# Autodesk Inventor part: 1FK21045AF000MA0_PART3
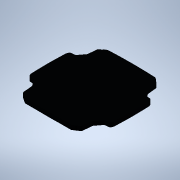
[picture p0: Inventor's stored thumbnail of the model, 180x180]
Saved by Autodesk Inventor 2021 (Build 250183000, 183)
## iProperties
Created: 2025-04
Part Number: 1FK21045AF000MA0_PART3
Material: Generic
Catalog Web Link: www.3dfindit.com
Description: -Servo synchronous motor
Document SubType Name: Modeling
Designer: psAdmin
Mass: 21.7019 g
Surface Area: 120.085 cm^2
Volume: 21.7019 cm^3
Density: 1 g/cm^3
Appearance: PSOLRGB-38-46-56
Category: PARTsolutions
Title: 1FK21045AF000MA0_PART3
Author: Cadenas PARTsolutions
Comments: Servo synchronous motor
Sending System: PARTsolutions
Preprocessor: ST-DEVELOPER v19.3
PSOL_IDENT_0: {$CADENAS_DATA/23d-libs/siemens_ag/_cat_/8b/0a/1fk21045af000ma0.prj},213 {VTYP=3D},{NB=1FK21045AF000
PSOL_IDENT_1: MA0_PART3},{LINA=1FK21045AF000MA0_PART3},{NN=1FK21045AF000MA0_PART3},{NOPRJ=TRUE},{DATE=19.08.2025 1
PSOL_IDENT_2: 4:00:48},{GEOMDATE=30.07.2025 02:00:28},{VERSION=},{LINEID=10},{WBVAR=},{WBNUMERIC=}  {NB=1FK21045AF
PSOL_IDENT_3: 000MA0_PART3},{LINA=1FK21045AF000MA0_PART3},{KT=DUMMY},{PREVIEW=../../../_pool_/a9/69/p_d211_xx_0081
PSOL_IDENT_4: 8j.png},{DESCSHORT=SIMOTICS S-1FK2 HD, SINAMICS S210 3AC 400V-480V, 2.4 Nm, 3000 rpm},{DESCLONG=SIMO
PSOL_IDENT_5: TICS S-1FK2 HD servo motor M0=2.4 Nm; PN = 0.75 kW at nN=3000 rpm (380-480 V); PN = 0.375 kW at nN=1
PSOL_IDENT_6: 500 rpm (200-240 V); degree of protection IP64; cylindrical shaft D19x40mm; absolute encoder 22-bit
PSOL_IDENT_7: + 12-bit multiturn (encoder AM22DQC); with OCC interface; plug size M17, rotatable; SIMOTICS S-1FK2
PSOL_IDENT_8: servomotorfor a wide range of uses in industrial environments. SIMOTICS S‑1FK2 servomotors are compa
PSOL_IDENT_9: ct synchronous motors with a high dynamic performance that set themselves apart as a result of their
PSOL_IDENT_10: high power density, degree of protection and overload capability. The motors are available in two v
PSOL_IDENT_11: ariants: as High Dynamic variant (highest dynamic performance as a result of the low intrinsic momen
PSOL_IDENT_12: t of inertia for applications demanding a high dynamic performance with low moved masses) - and as C
PSOL_IDENT_13: ompact variant (precise and stable closed-loop control for medium up to large moved masses as a resu
PSOL_IDENT_14: lt of a medium intrinsic moment of inertia). SIMOTICSS‑1FK2 servomotors fully exploit their strength
PSOL_IDENT_15: s in a system with the SINAMICSS210 frequency converter and simple connection using the one cable co
PSOL_IDENT_16: nnection (OCC). Advantages include the short control and positioning times, fast and precise correct
PSOL_IDENT_17: ion of disturbing quantities as well as stable control with a high dynamic performance. The servo mo
PSOL_IDENT_18: tors can be configured to address a wide range of requirements. For example with and without holding
PSOL_IDENT_19: brake, IP64 or IP65 degree of protection, singleturn or multiturn absolute encoders - to name just
PSOL_IDENT_20: a few. Further, the servomotors are available in different shaft heights extending from 20 to 100. A
PSOL_IDENT_21: shaft sealing ring is available to achieve an IP65 degree of protection and for subsequent mounting
PSOL_IDENT_22: at the motor or as spare part. SIMOTICS - the optimum motor for each and every motion control appli
PSOL_IDENT_23: cation.},{INTNO=195125050112},{SUPPLIERALTNO=1FK2104-5AF00-0MA0},{MANUID=1FK21045AF000MA0},{MANUNAME=
PSOL_IDENT_24: Siemens},{MANUTYPEDESC=Synchronous motor 1FK2-HD 2.4 NM},{AAU732=SIMOTICS},{AAO057=S-1FK2},{AAU734=S
PSOL_IDENT_25: IMOTICS S-1FK2 HD servo motor M0=2.4 Nm; PN = 0.75 kW at nN=3000 rpm (380-480 V); PN = 0.375 kW at n
PSOL_IDENT_26: N=1500 rpm (200-240 V); degree of protection IP64; cylindrical shaft D19x40mm; absolute encoder 22-b
PSOL_IDENT_27: it + 12-bit multiturn (encoder AM22DQC); with OCC interface; plug size M17, rotatable;},{AAW338=Sync
PSOL_IDENT_28: hronous motor 1FK2-HD 2.4 NM},{AAO742=SIMOTICS},{AAO663=4042948692912},{NOCUPEROU=1},{PRICEQUANTITY=
PSOL_IDENT_29: 1},{QUANTITYMIN=1},{QUANTITYINT=1},{CTN=85015100},{COO=DE},{AAO676=1FK2104-5AF00-0MA0},{AAO677=Sieme
PSOL_IDENT_30: ns AG},{ORDERUNIT=C62},{CONTENTUNIT=C62}
NB: 1FK21045AF000MA0_PART3
NT: Servo synchronous motor
NBSYN: $MANUID._PART3
LINA: 1FK21045AF000MA0_PART3
CATALOG: SIEMENS
PREVIEW: ../../../_pool_/a9/69/p_d211_xx_00818j.png
DESCSHORT: SIMOTICS S-1FK2 HD, SINAMICS S210 3AC 400V-480V, 2.4 Nm, 3000 rpm
DESCLONG: SIMOTICS S-1FK2 HD servo motor M0=2.4 Nm; PN = 0.75 kW at nN=3000 rpm (380-480 V); PN = 0.375 kW at nN=1500 rpm (200-240 V); degree of protection IP64; cylindri
INTNO: 195125050112
SUPPLIERALTNO: 1FK2104-5AF00-0MA0
MANUID: 1FK21045AF000MA0
MANUNAME: Siemens
MANUTYPEDESC: Synchronous motor 1FK2-HD 2.4 NM
AAU732: SIMOTICS
AAO057: S-1FK2
AAU734: SIMOTICS S-1FK2 HD servo motor M0=2.4 Nm; PN = 0.75 kW at nN=3000 rpm (380-480 V); PN = 0.375 kW at nN=1500 rpm (200-240 V); degree of protection IP64; cylindri
AAW338: Synchronous motor 1FK2-HD 2.4 NM
AAO742: SIMOTICS
AAO663: 4042948692912.0
NOCUPEROU: 1
PRICEQUANTITY: 1
QUANTITYMIN: 1
QUANTITYINT: 1
CTN: 85015100
COO: DE
ARTICLENO: 1FK21045AF000MA0_PART3
BOMINFO: 1FK21045AF000MA0_PART3
CREATOR: CADENAS GmbH
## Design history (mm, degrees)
feature "2025_04_17_15_40_42_0672"
body "Solid1"
